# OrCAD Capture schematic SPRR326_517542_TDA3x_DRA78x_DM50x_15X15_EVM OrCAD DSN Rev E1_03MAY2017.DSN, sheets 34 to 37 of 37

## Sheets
34 SH12 - MUX D/E/F/G/H: size C; rev: A
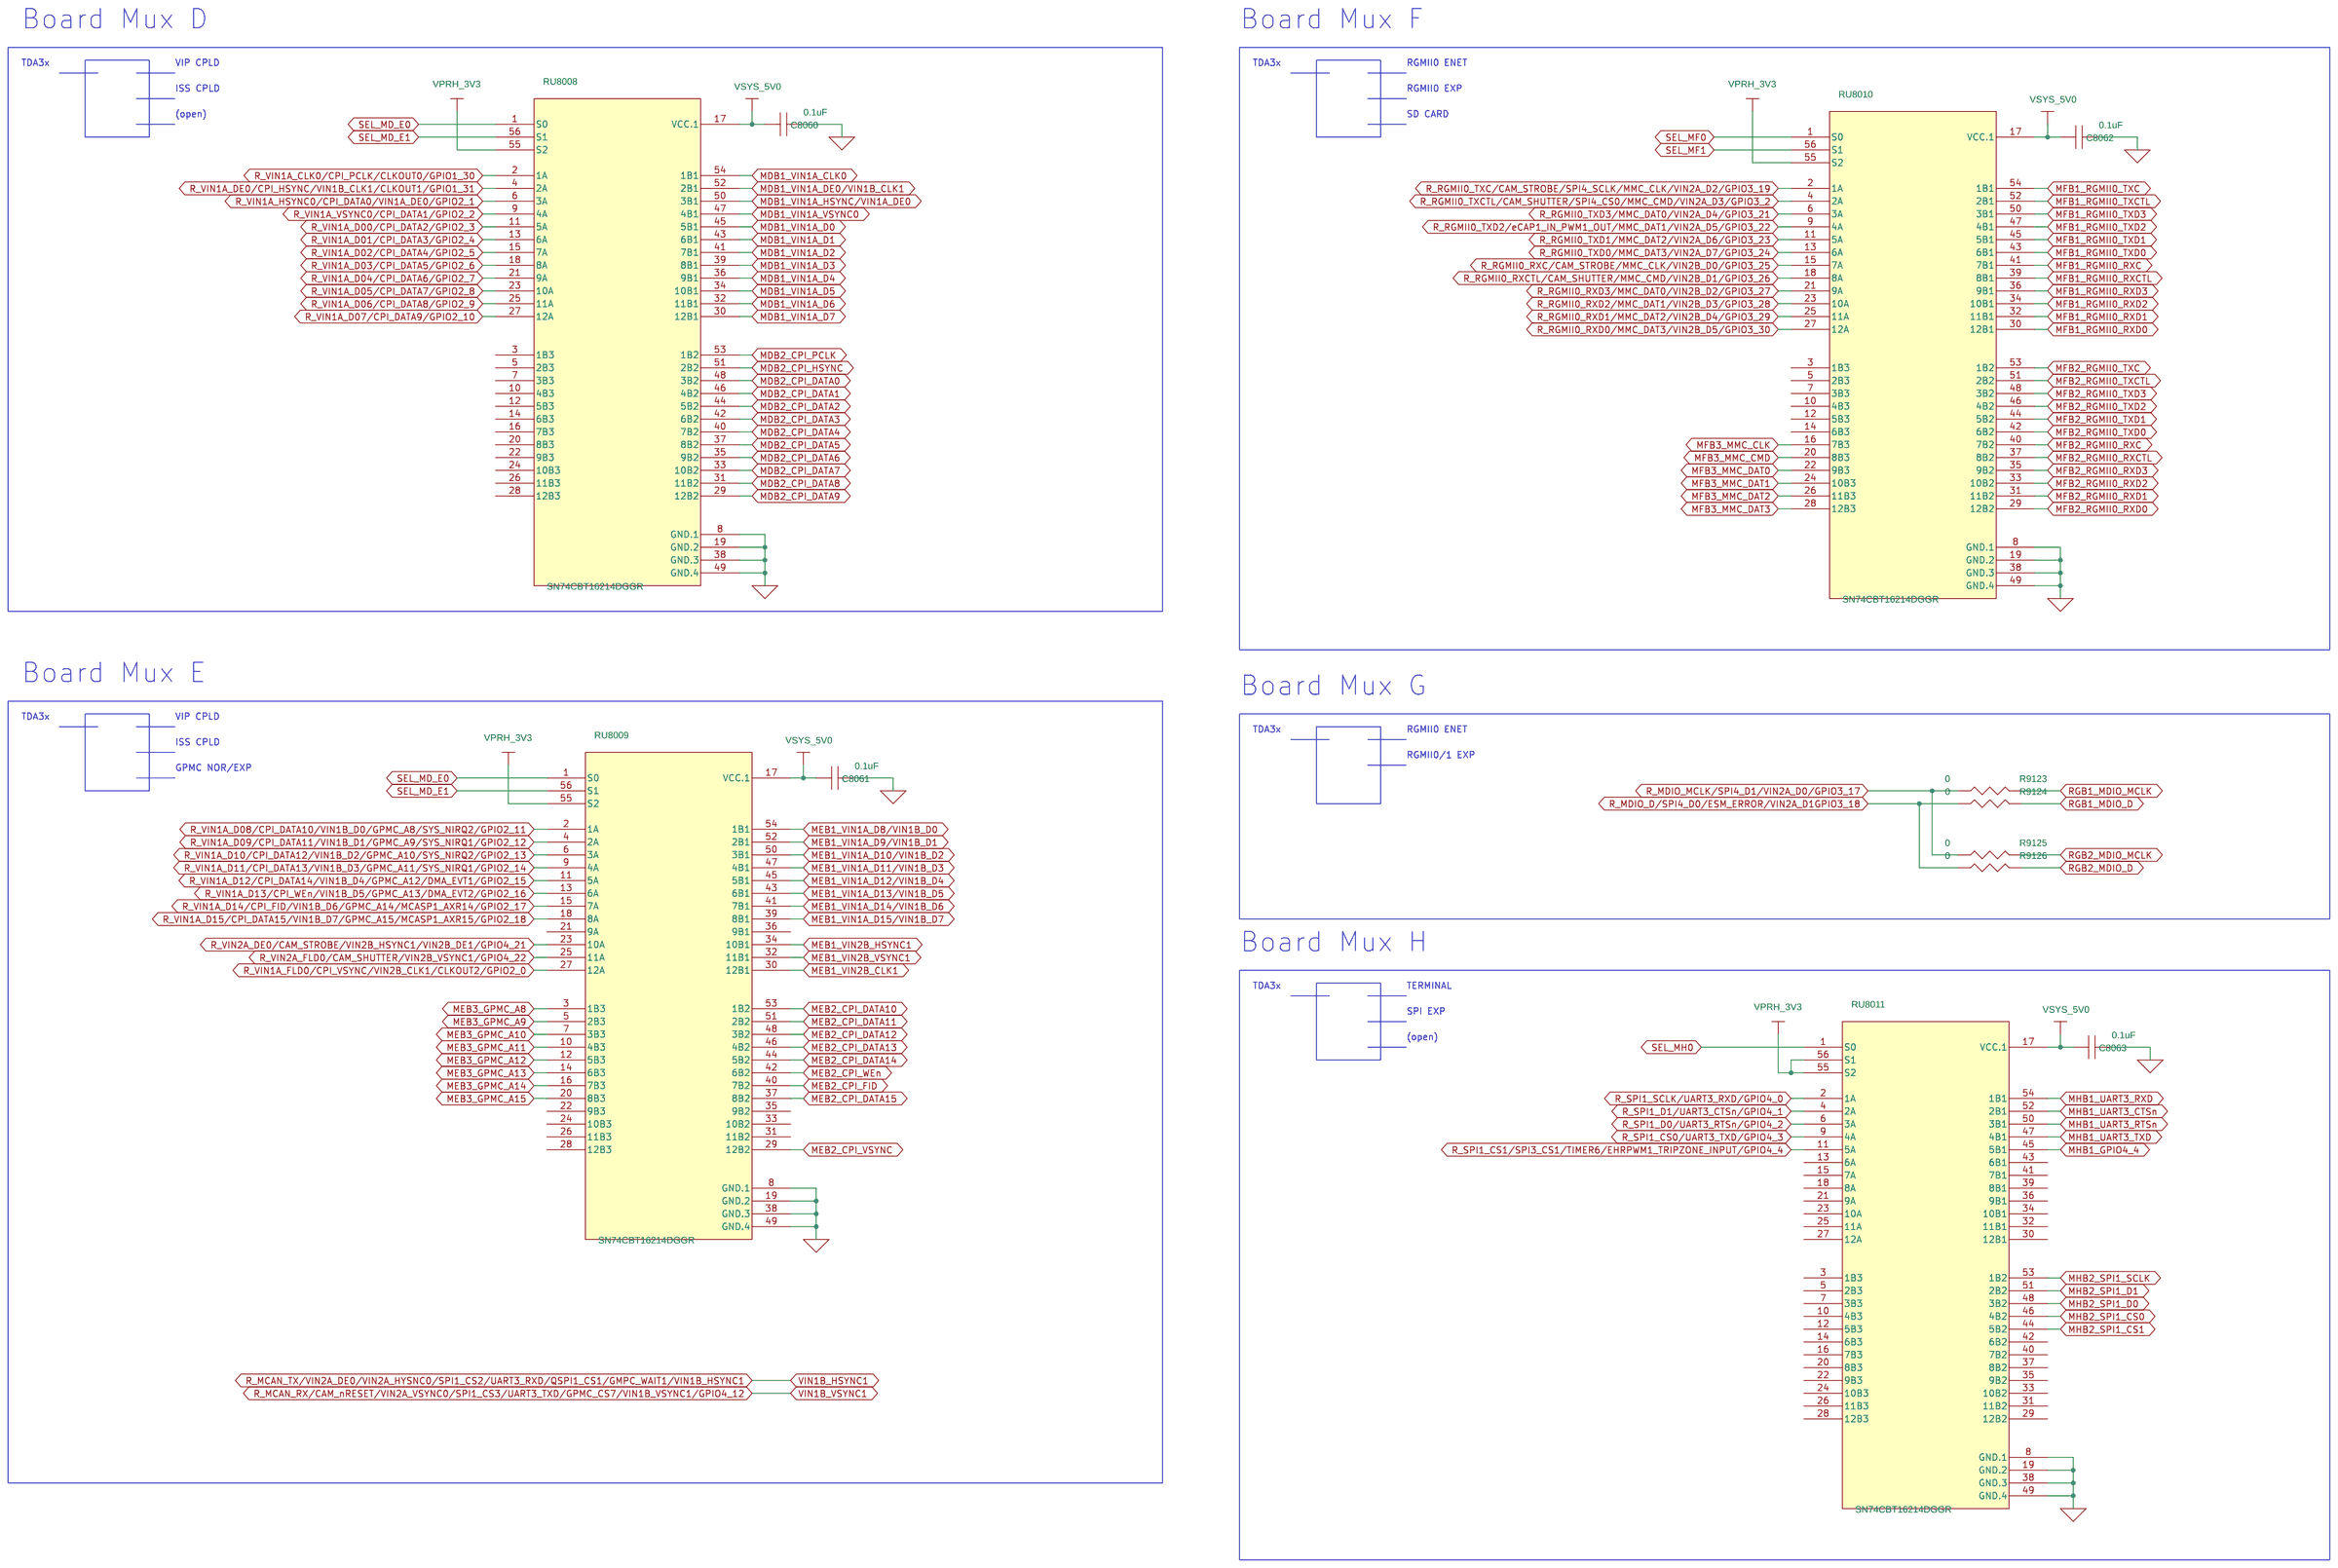
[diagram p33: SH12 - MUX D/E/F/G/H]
35 SH17 - CAN/SAFETY MCU: size C; rev: D
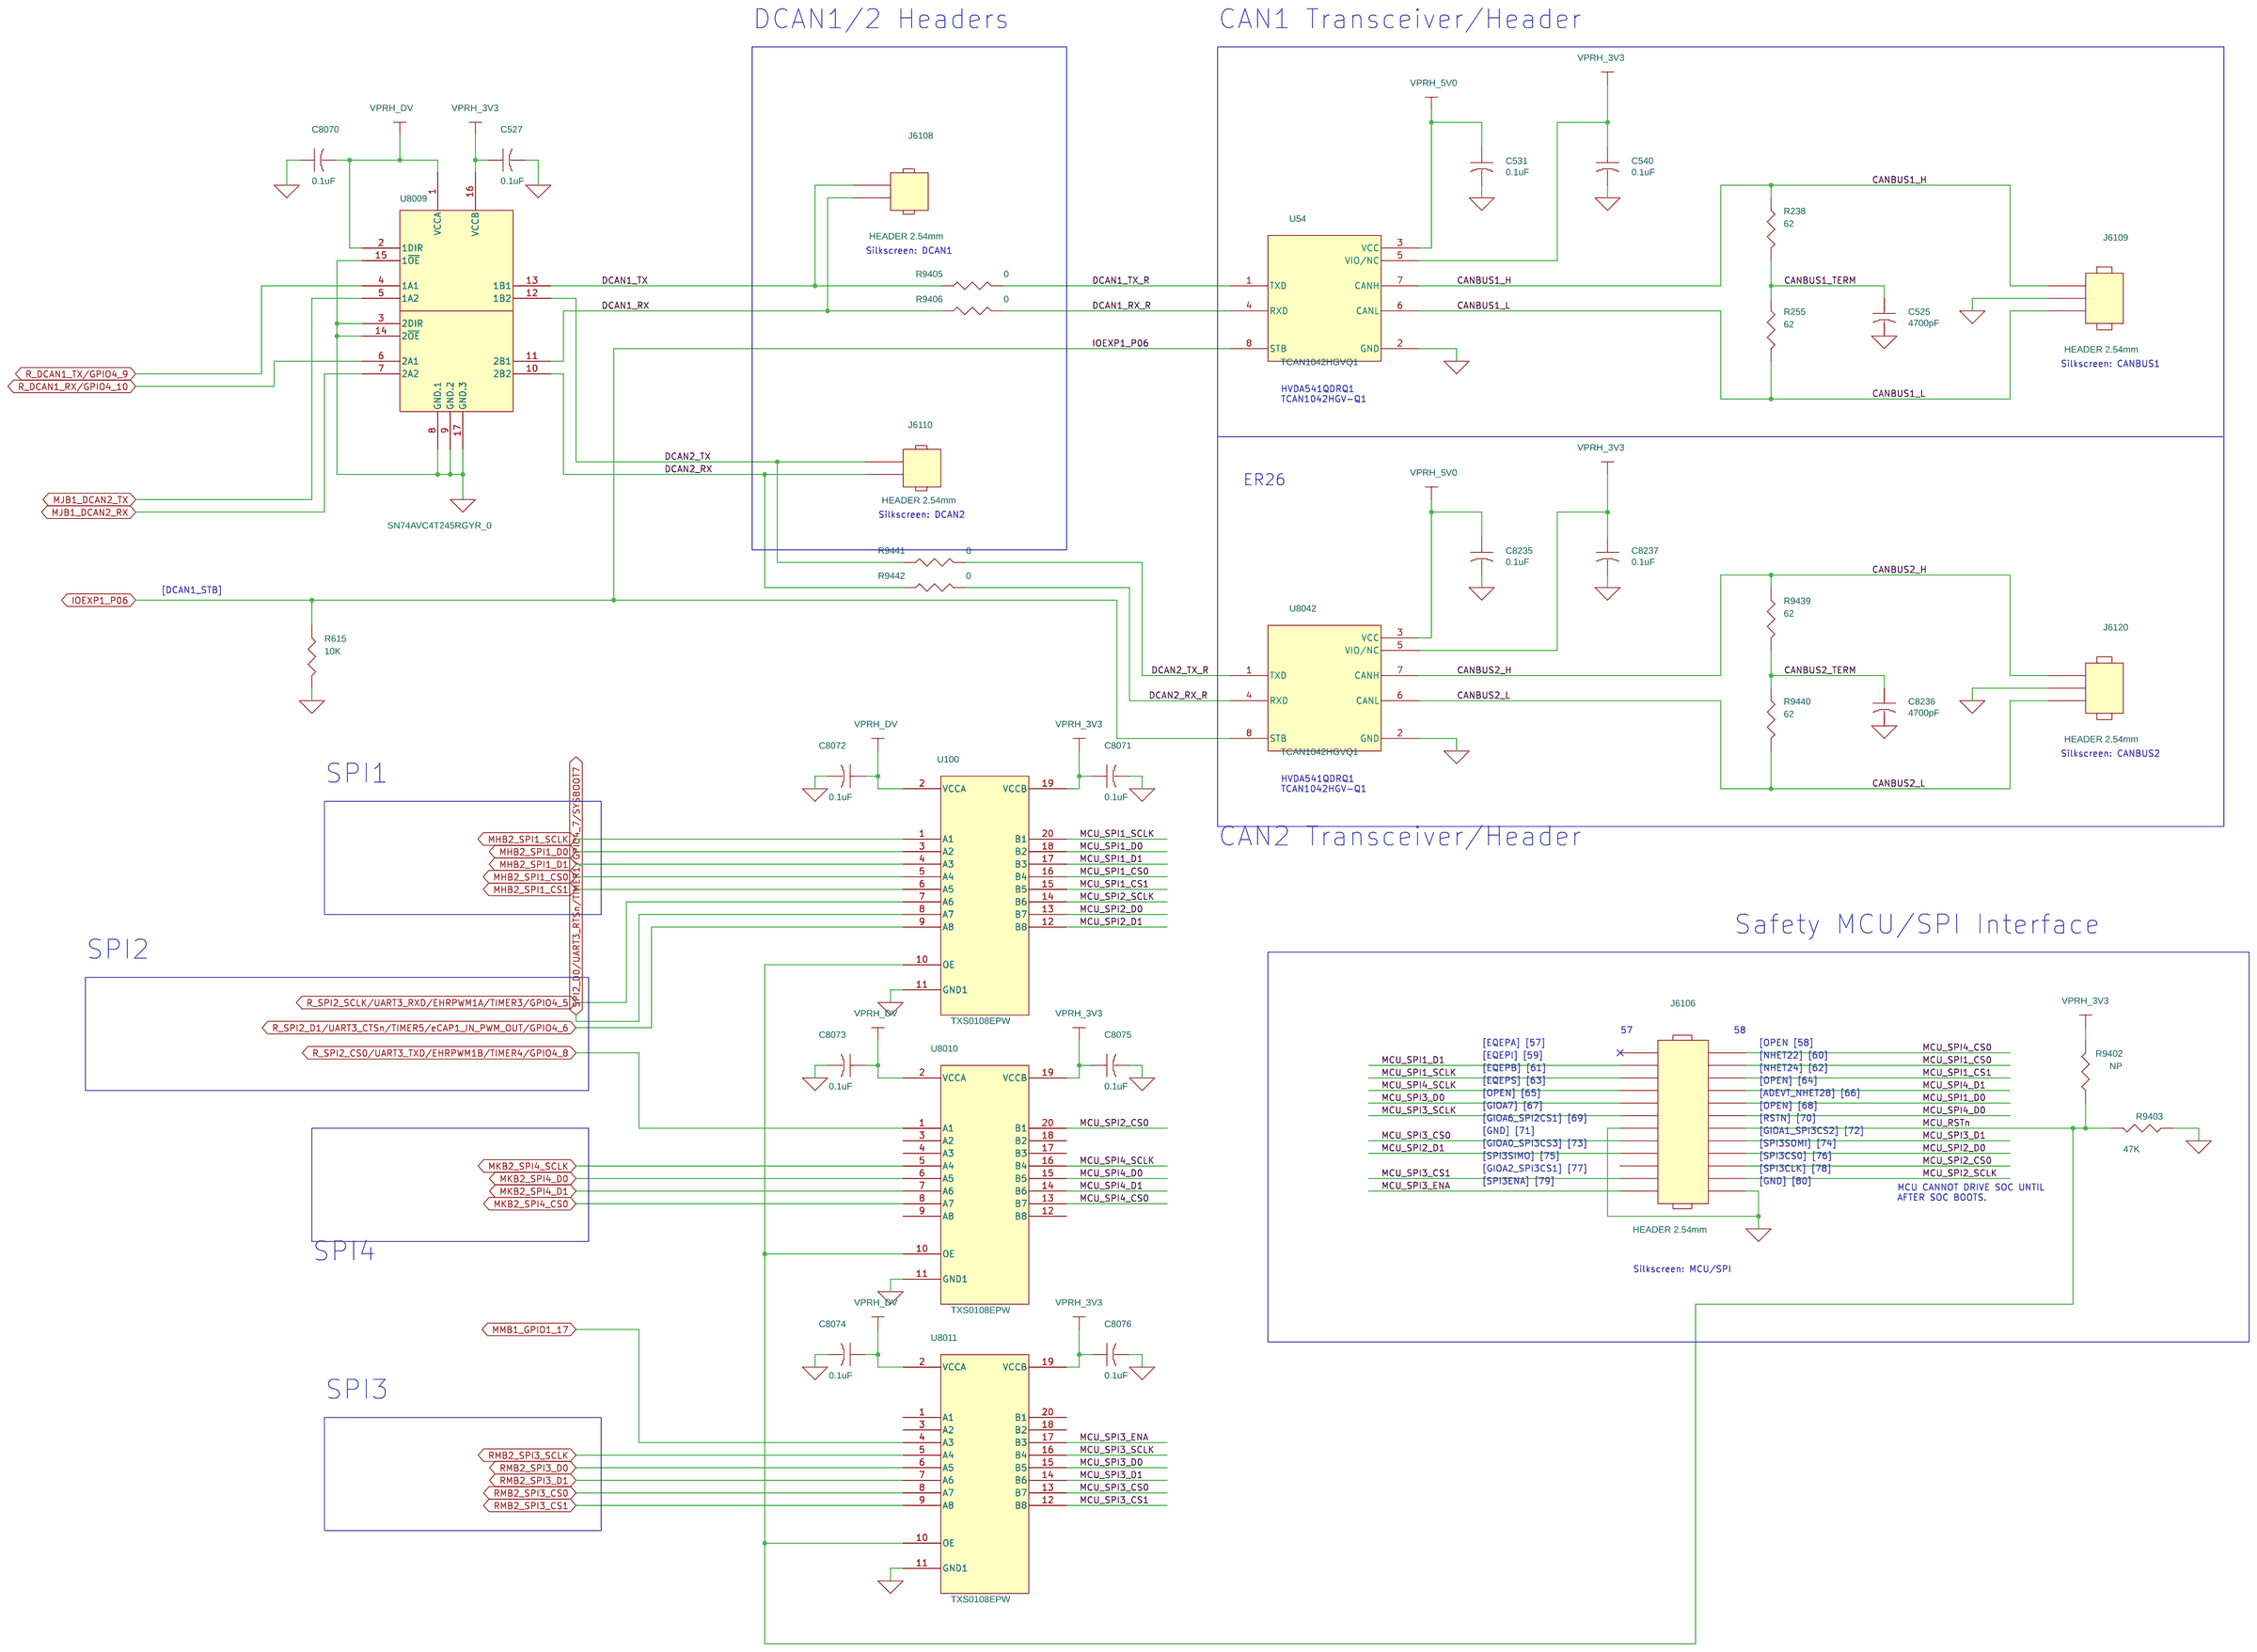
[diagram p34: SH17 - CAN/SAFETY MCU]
36 SH14 - SD CARD/EEPROM/TMP: size C; rev: D
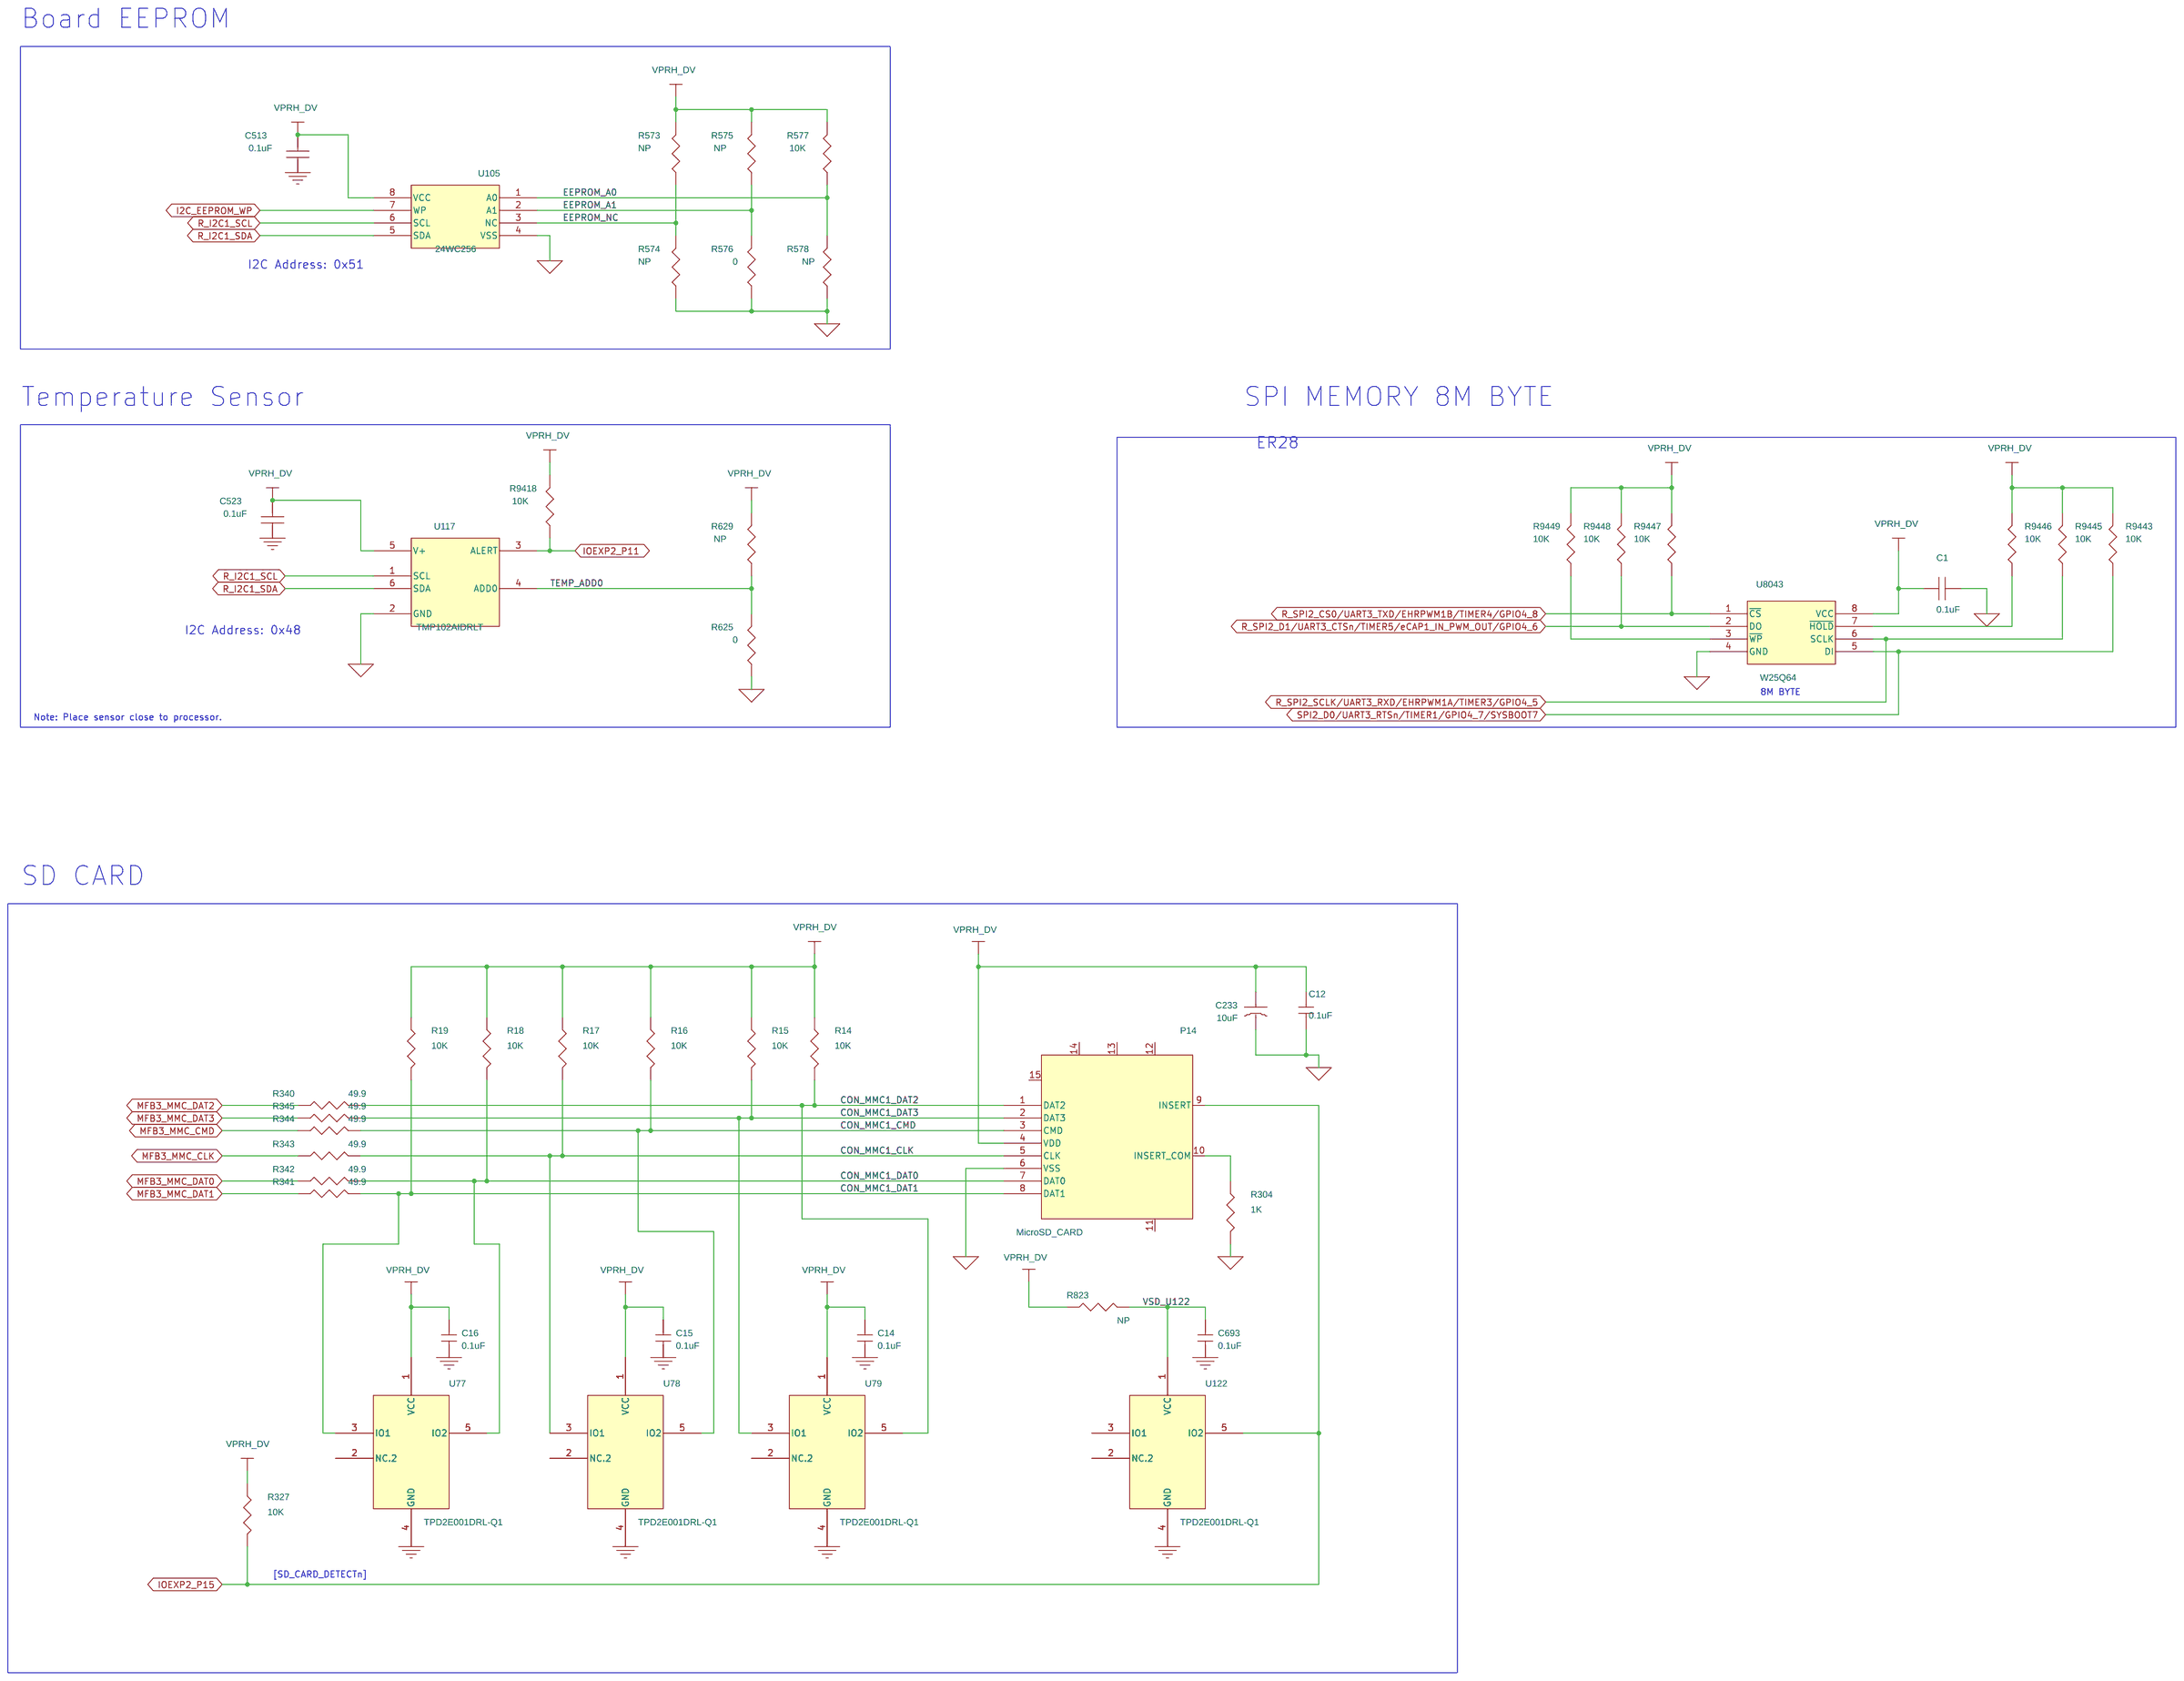
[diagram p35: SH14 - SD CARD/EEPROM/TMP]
37 SH23 - POWER BENCH/MONITORS: size C; rev: A
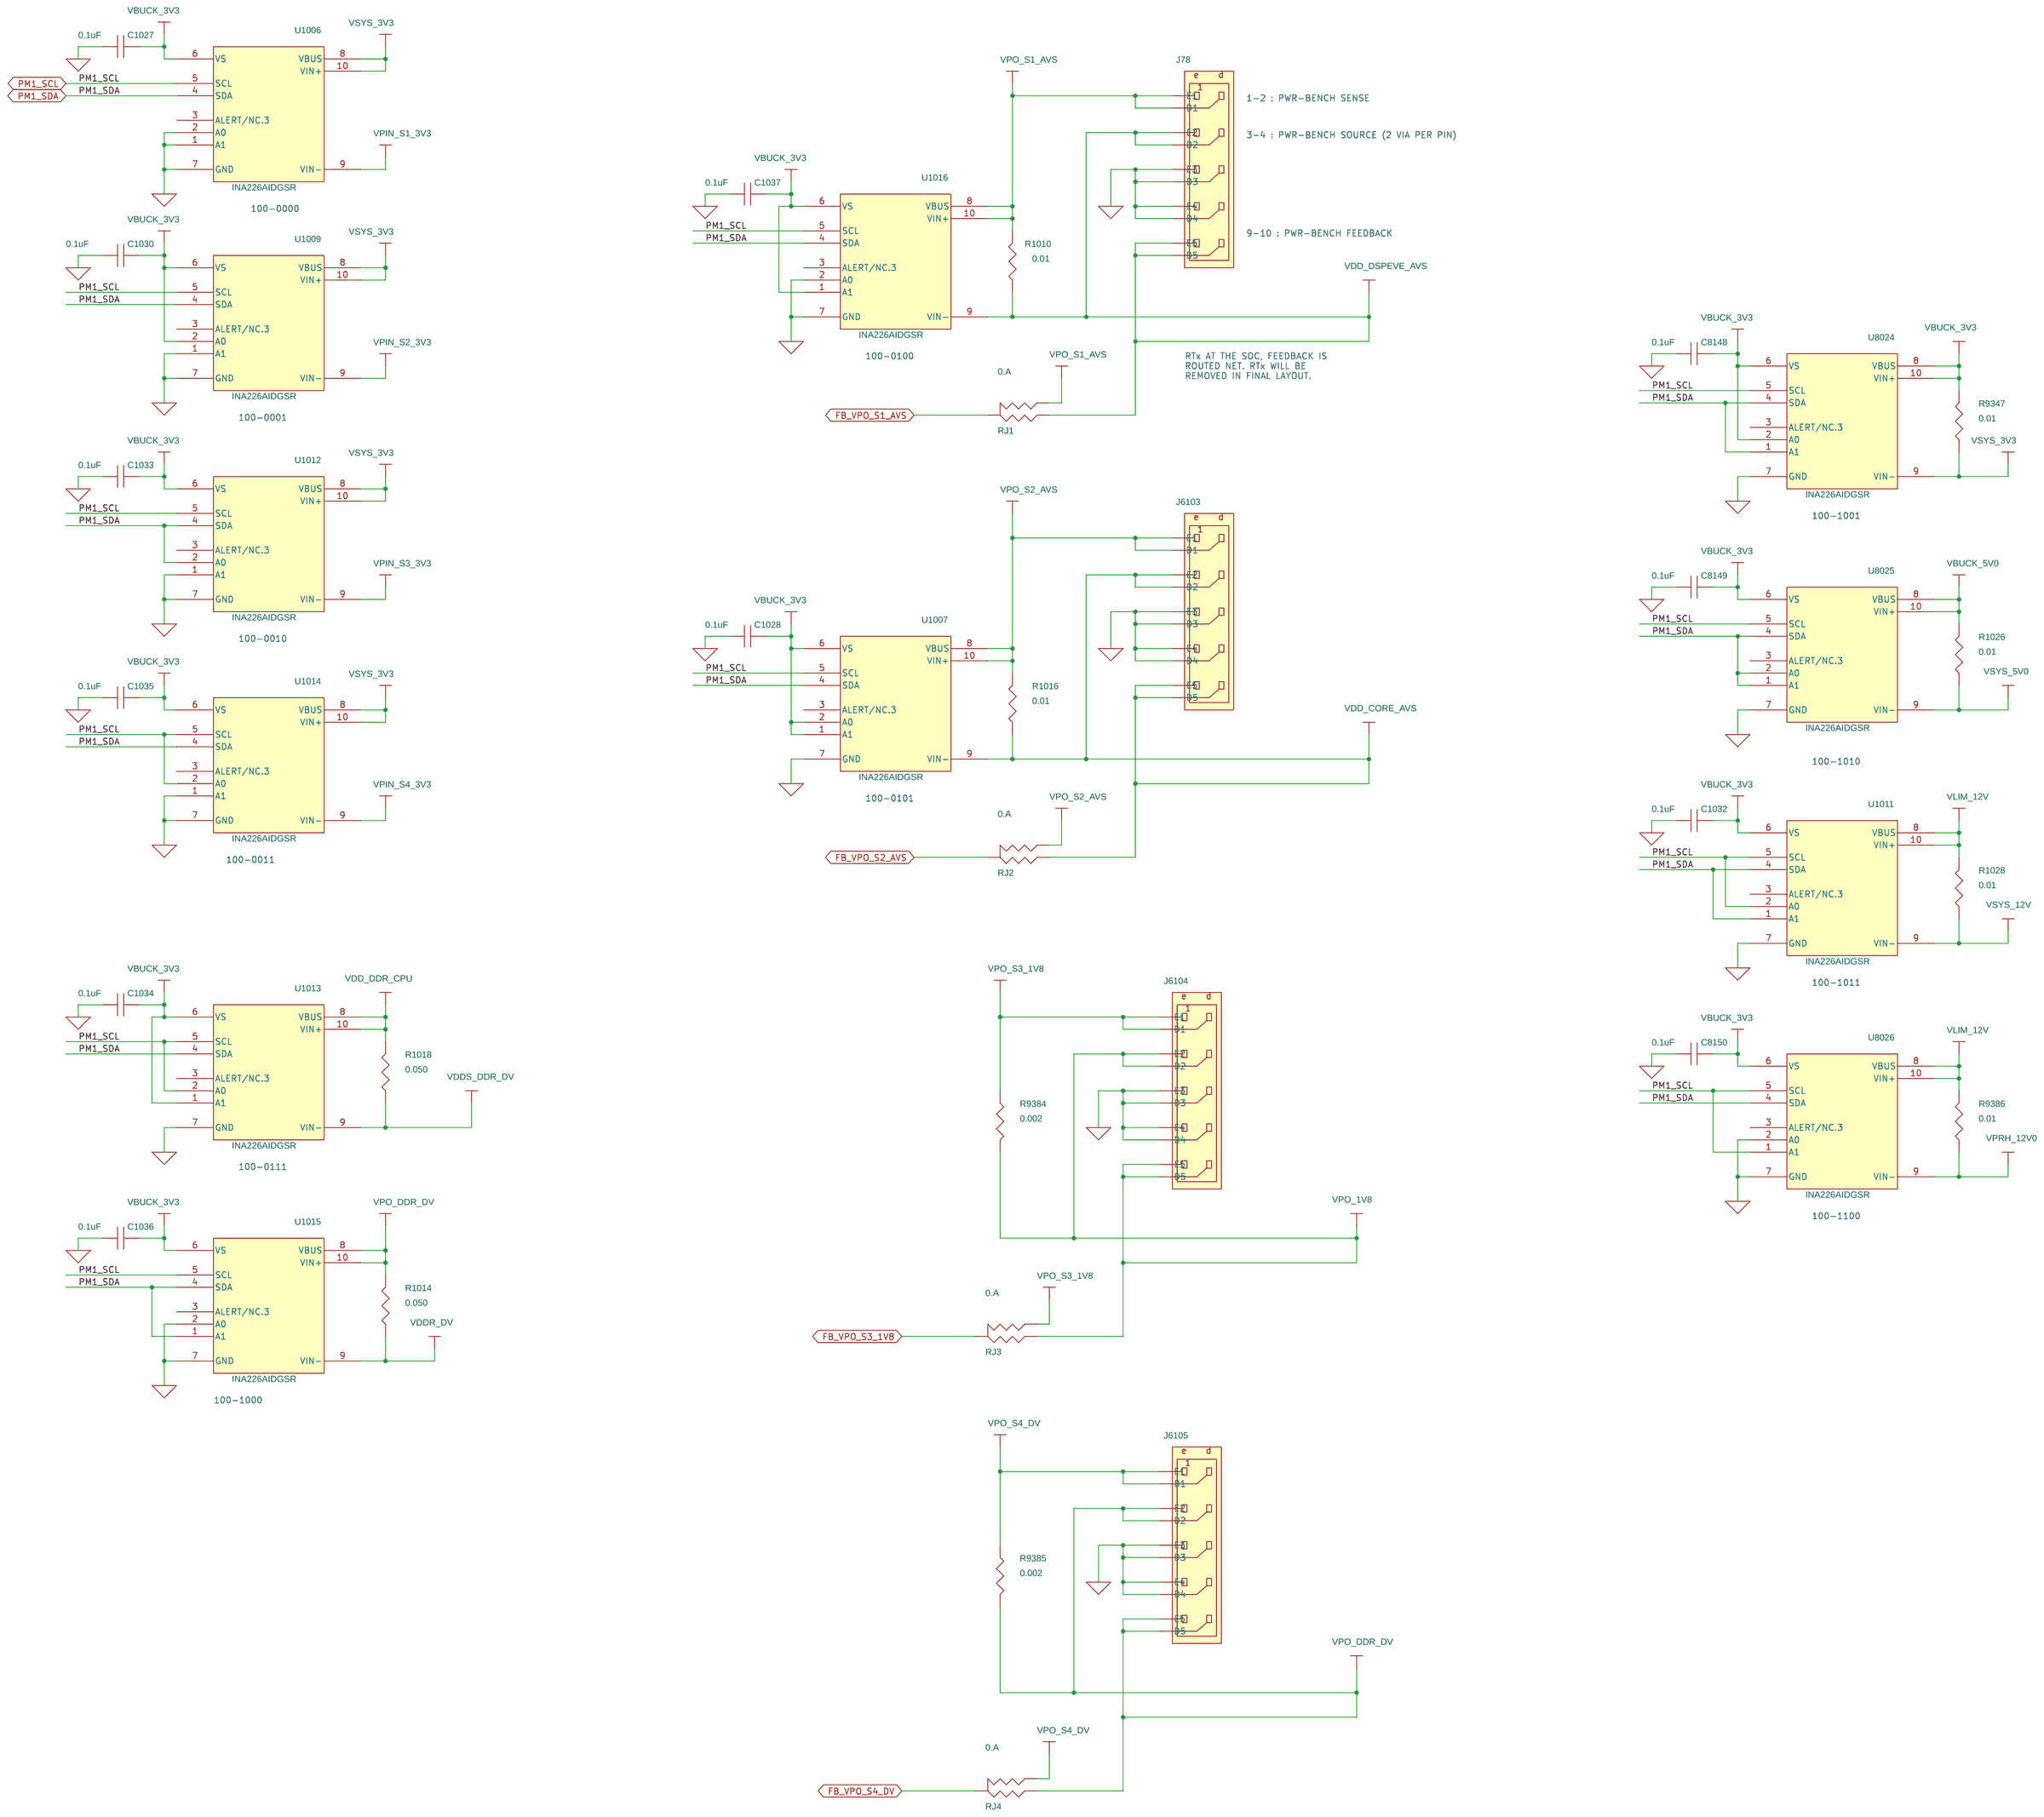
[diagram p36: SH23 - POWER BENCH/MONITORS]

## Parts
sheet SH12 - MUX D/E/F/G/H
C8060  0.1uF  [c402-25]
C8061  0.1uF  [c402-25]
C8062  0.1uF  [c402-25]
C8063  0.1uF  [c402-25]
R9123  0  [r201-6p6spc]
R9124  0  [r201-6p6spc]
R9125  0  [r201-6p6spc]
R9126  0  [r201-6p6spc]
RU8008  SN74CBT16214DGGR  [dgg56-12x80]
RU8009  SN74CBT16214DGGR  [dgg56-12x80]
RU8010  SN74CBT16214DGGR  [dgg56-12x80]
RU8011  SN74CBT16214DGGR  [dgg56-12x80]
sheet SH14 - SD CARD/EEPROM/TMP
C1  0.1uF  [c402-25]
C12  0.1uF  [c402-25]
C14  0.1uF  [c402-25]
C15  0.1uF  [c402-25]
C16  0.1uF  [c402-25]
C233  10uF  [c603-35x45]
C513  0.1uF  [c402-25]
C523  0.1uF  [c402-25]
C693  0.1uF  [c402-25]
P14  MicroSD_CARD  [molex-49225-201]
R14  10K  [r402-25]
R15  10K  [r402-25]
R16  10K  [r402-25]
R17  10K  [r402-25]
R18  10K  [r402-25]
R19  10K  [r402-25]
R304  1K  [r402-25]
R327  10K  [r402-25]
R340  49.9  [r402-25]
R341  49.9  [r402-25]
R342  49.9  [r402-25]
R343  49.9  [r402-25]
R344  49.9  [r402-25]
R345  49.9  [r402-25]
R573  NP  [r402-25]
R574  NP  [r402-25]
R575  NP  [r402-25]
R576  0  [r402-25]
R577  10K  [r402-25]
R578  NP  [r402-25]
R625  0  [r402-25]
R629  NP  [r402-25]
R823  NP  [r402-25]
R9418  10K  [r402-25]
R9443  10K  [r201-18p5x15]
R9445  10K  [r201-18p5x15]
R9446  10K  [r201-18p5x15]
R9447  10K  [r201-18p5x15]
R9448  10K  [r201-18p5x15]
R9449  10K  [r201-18p5x15]
U77  TPD2E001DRL-Q1  [drl5-12x40]
U78  TPD2E001DRL-Q1  [drl5-12x40]
U79  TPD2E001DRL-Q1  [drl5-12x40]
U105  24WC256  [so8-25x75-295]
U117  TMP102AIDRLT  [drl6-12x30]
U122  TPD2E001DRL-Q1  [drl5-12x40]
U8043  W25Q64  [so8-25x75-295]
sheet SH17 - CAN/SAFETY MCU
C525  4700pF  [c402-25]
C527  0.1uF  [c402-25]
C531  0.1uF  [c402-25]
C540  0.1uF  [c402-25]
C8070  0.1uF  [c402-25]
C8071  0.1uF  [c402-25]
C8072  0.1uF  [c402-25]
C8073  0.1uF  [c402-25]
C8074  0.1uF  [c402-25]
C8075  0.1uF  [c402-25]
C8076  0.1uF  [c402-25]
C8235  0.1uF  [c402-25]
C8236  4700pF  [c402-25]
C8237  0.1uF  [c402-25]
J6106  HEADER 2.54mm  [jump2x12-6040]
J6108  HEADER 2.54mm  [JUMP1X2-6040]
J6109  HEADER 2.54mm  [JUMP1X3-6040]
J6110  HEADER 2.54mm  [JUMP1X2-6040]
J6120  HEADER 2.54mm  [JUMP1X3-6040]
R238  62  [r1206-40x70]
R255  62  [r1206-40x70]
R615  10K  [r402-25]
R9402  NP  [r402-25]
R9403  47K  [r402-25]
R9405  0  [r402-25]
R9406  0  [r402-25]
R9439  62  [r1206-40x70]
R9440  62  [r1206-40x70]
R9441  0  [r402-25]
R9442  0  [r402-25]
U54  TCAN1042HGVQ1  [so8-25x75]
U100  TXS0108EPW  [pw20-14x70]
U8009  SN74AVC4T245RGYR_0  [rgy16-12x34]
U8010  TXS0108EPW  [pw20-14x70]
U8011  TXS0108EPW  [pw20-14x70]
U8042  TCAN1042HGVQ1  [so8-25x75]
sheet SH23 - POWER BENCH/MONITORS
C1027  0.1uF  [c402-25]
C1028  0.1uF  [c402-25]
C1030  0.1uF  [c402-25]
C1032  0.1uF  [c402-25]
C1033  0.1uF  [c402-25]
C1034  0.1uF  [c402-25]
C1035  0.1uF  [c402-25]
C1036  0.1uF  [c402-25]
C1037  0.1uF  [c402-25]
C8148  0.1uF  [c402-25]
C8149  0.1uF  [c402-25]
C8150  0.1uF  [c402-25]
J78  Qte=0.5  [conn2x5-40x100-tsm]
J6103  Qte=0.5  [conn2x5-40x100-tsm]
J6104  Qte=0.5  [conn2x5-40x100-tsm]
J6105  Qte=0.5  [conn2x5-40x100-tsm]
R1010  0.01  [r1206-40X70]
R1014  0.050  [r603-35x45]
R1016  0.01  [r1206-40X70]
R1018  0.050  [r603-35x45]
R1026  0.01  [r1206-40X70]
R1028  0.01  [r1206-40X70]
R9347  0.01  [r1206-40X70]
R9384  0.002  [r1206-40x70]
R9385  0.002  [r1206-40x70]
R9386  0.01  [r1206-40X70]
RJ1  0.A  [JMP402-25]
RJ2  0.A  [JMP402-25]
RJ3  0.A  [JMP402-25]
RJ4  0.A  [JMP402-25]
U1006  INA226AIDGSR  [dgs10-11x60]
U1007  INA226AIDGSR  [dgs10-11x60]
U1009  INA226AIDGSR  [dgs10-11x60]
U1011  INA226AIDGSR  [dgs10-11x60]
U1012  INA226AIDGSR  [dgs10-11x60]
U1013  INA226AIDGSR  [dgs10-11x60]
U1014  INA226AIDGSR  [dgs10-11x60]
U1015  INA226AIDGSR  [dgs10-11x60]
U1016  INA226AIDGSR  [dgs10-11x60]
U8024  INA226AIDGSR  [dgs10-11x60]
U8025  INA226AIDGSR  [dgs10-11x60]
U8026  INA226AIDGSR  [dgs10-11x60]

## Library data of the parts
C1027 C1028 C1030 C1032-C1037 C8060-C8063 C8148-C8150 = CAP_NP: Part #: 104446-1100R
R9123-R9126 = R_1: Part #: 103158-0001R
RU8008-RU8011 = SN74CBT16214DGGR_0: Part #: 102513-0001R
C1 = CAP_NP: Part #: 101587-1100R
C12 C14-C16 C693 = Cap_100nF_Cermc_16V_10%_603_4: Part #: 104446-1100R
C233 = CAP: Part #: 102963-0101R
C513 C523 = CAP_.1_uF_10%_0603: Part #: 104446-1100R
P14 = MM_CARD_0: Part #: 103053-0001R
R14-R19 R327 = RESISTOR: Part #: 101370-1003R
R304 = RESISTOR: Part #: 101370-1002R
R340-R345 = RESISTOR: Part #: 102145-4990R
R573-R575 R629 R9402 = R: Part #: R0402-NOPOP
R576 R625 = R_1: Part #: 101370-0001R
R577 R615 R9418 = R: Part #: 101370-1003R
R578 = R_1: Part #: R0402-NOPOP
R823 = RESISTOR: Part #: R0402-NOPOP
R9443 R9447-R9449 = R: Part #: 103158-1003R
R9445 R9446 = RESISTOR_1: Part #: 103158-1003R
U77-U79 U122 = TPDE0001RSE_0: Part #: 102728-0001R
U105 = 24WC256: Part #: 102235-0001R
U117 = TMP102AIDRLT: Part #: 104192-0001R
U8043 = SPI_EEPROM_2: Part #: 104052-0001R
C525 C8236 = CAP: Part #: 103217-1472R
C527 C531 C540 C8070-C8076 C8235 C8237 = CAP: Part #: 104446-1100R
J6106 = HEADER_12X2: Part #: 100116-0012R
J6108 J6110 = HEADER_2: Part #: 100115-0002R
J6109 J6120 = HEADER_3: Part #: NO-POP
R238 R255 R9439 R9440 = R: Part #: 100155-6200R
R9403 = R: Part #: 101370-4703R
R9405 R9406 R9441 R9442 = R: Part #: 101370-0001R
U54 U8042 = SN65HVDA541: Part #: 104828-0001R
U100 U8010 U8011 = TXB0108PWR_0: Part #: 103666-0001R
U8009 = SN74AVC4T245RGYR_0: Part #: 102649-0245R
J78 J6103-J6105 = HE10_10MD_ASP-128562-04_0: GPAO_ART: 05600038255AA; Part #: 100932-0005R
R1010 R1016 R1026 R1028 R9347 R9386 = R: Part #: 102598-0001R
R1014 R1018 = R: Part #: 104469-0005R
R9384 R9385 = R: Part #: 104297-0002R
RJ1-RJ4 = RJUMP3: Part #: 101370-0001R
U1006 U1007 U1009 U1011-U1016 U8024-U8026 = INA220IDCN_2: Part #: 103928-0001R

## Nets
GND: C1.2 C12.2 C14.2 C15.2 C16.2 C233.2 C513.1 C523.1 C525.2 C527.2 C531.2 C540.2 C693.2 C1027.1 C1028.1 C1030.1 C1032.1 C1033.1 C1034.1 C1035.1 C1036.1 C1037.1 C8060.2 C8061.2 C8062.2 C8063.2 C8070.1 C8071.2 C8072.2 C8073.2 C8074.2 C8075.2 C8076.2 C8148.1 C8149.1 C8150.1 C8235.2 C8236.2 C8237.2 J78.5(E3) J78.6(D3) J78.7(E4) J78.8(D4) J6103.5(E3) J6103.6(D3) J6103.7(E4) J6103.8(D4) J6104.5(E3) J6104.6(D3) J6104.7(E4) J6104.8(D4) J6105.5(E3) J6105.6(D3) J6105.7(E4) J6105.8(D4) J6106.13 J6106.24 J6109.2 J6120.2 P14.6(VSS) R304.2 R574.2 R576.2 R578.2 R615.2 R625.2 R9403.2 RU8008.8(GND.1) RU8008.19(GND.2) RU8008.38(GND.3) RU8008.49(GND.4) RU8009.8(GND.1) RU8009.19(GND.2) RU8009.38(GND.3) RU8009.49(GND.4) RU8010.8(GND.1) RU8010.19(GND.2) RU8010.38(GND.3) RU8010.49(GND.4) RU8011.8(GND.1) RU8011.19(GND.2) RU8011.38(GND.3) RU8011.49(GND.4) U54.2(GND) U77.4(GND) U78.4(GND) U79.4(GND) U100.11(GND1) U105.4(VSS) U117.2(GND) U122.4(GND) U1006.1(A1) U1006.2(A0) U1006.7(GND) U1007.7(GND) U1009.1(A1) U1009.7(GND) U1011.7(GND) U1012.1(A1) U1012.7(GND) U1013.7(GND) U1014.1(A1) U1014.7(GND) U1015.2(A0) U1015.7(GND) U1016.2(A0) U1016.7(GND) U8009.3(2DIR) U8009.8(GND.1) U8009.9(GND.2) U8009.14(2~{OE}) U8009.15(1~{OE}) U8009.17(GND.3) U8010.11(GND1) U8011.11(GND1) U8024.7(GND) U8025.7(GND) U8026.2(A0) U8026.7(GND) U8042.2(GND) U8043.4(GND) ; also on sheet 4 5 6 7 8 9 10 11 12 13 14 15 16 17 18 19 20 21 22 23 25 26 27 28 29 30 31 32
MDB1_VIN1A_DE0/VIN1B_CLK1: RU8008.52(2B1) ; also on sheet 27
MDB1_VIN1A_HSYNC/VIN1A_DE0: RU8008.50(3B1) ; also on sheet 27
MEB1_VIN1A_D8/VIN1B_D0: RU8009.54(1B1) ; also on sheet 27
MEB1_VIN1A_D9/VIN1B_D1: RU8009.52(2B1) ; also on sheet 27
MEB1_VIN1A_D10/VIN1B_D2: RU8009.50(3B1) ; also on sheet 27
MEB1_VIN1A_D11/VIN1B_D3: RU8009.47(4B1) ; also on sheet 27
MEB1_VIN1A_D12/VIN1B_D4: RU8009.45(5B1) ; also on sheet 27
MEB1_VIN1A_D13/VIN1B_D5: RU8009.43(6B1) ; also on sheet 27
MEB1_VIN1A_D14/VIN1B_D6: RU8009.41(7B1) ; also on sheet 27
MEB1_VIN1A_D15/VIN1B_D7: RU8009.39(8B1) ; also on sheet 27
R_MDIO_D/SPI4_D0/ESM_ERROR/VIN2A_D1GPIO3_18: R9124.2 R9126.2 ; also on sheet 7
VDD_CORE_AVS: J6103.3(E2) J6103.4(D2) J6103.9(E5) J6103.10(D5) R1016.2 RJ2.1 U1007.9(VIN-) ; also on sheet 4 5
VDD_DDR_CPU: R1018.1 U1013.8(VBUS) U1013.10(VIN+) ; also on sheet 14
VDD_DSPEVE_AVS: J78.3(E2) J78.4(D2) J78.9(E5) J78.10(D5) R1010.2 RJ1.1 U1016.9(VIN-) ; also on sheet 4 5
VDDR_DV: R1014.2 U1015.9(VIN-) ; also on sheet 6
VDDS_DDR_DV: R1018.2 U1013.9(VIN-) ; also on sheet 5
CANBUS1_H: J6109.1 R238.1 U54.7(CANH)
CANBUS1_L: J6109.3 R255.2 U54.6(CANL)
CANBUS1_TERM: C525.1 R238.2 R255.1
CANBUS2_H: J6120.1 R9439.1 U8042.7(CANH)
CANBUS2_L: J6120.3 R9440.2 U8042.6(CANL)
CANBUS2_TERM: C8236.1 R9439.2 R9440.1
CON_MMC1_CLK: P14.5(CLK) R17.2 R343.2 U78.3(IO1)
CON_MMC1_CMD: P14.3(CMD) R16.2 R344.2 U78.5(IO2)
CON_MMC1_DAT0: P14.7(DAT0) R18.2 R342.2 U77.5(IO2)
CON_MMC1_DAT1: P14.8(DAT1) R19.2 R341.2 U77.3(IO1)
CON_MMC1_DAT2: P14.1(DAT2) R14.2 R340.2 U79.5(IO2)
CON_MMC1_DAT3: P14.2(DAT3) R15.2 R345.2 U79.3(IO1)
DCAN1_RX: J6108.2 R9406.1 U8009.11(2B1)
DCAN1_RX_R: R9406.2 U54.4(RXD)
DCAN1_TX: J6108.1 R9405.1 U8009.13(1B1)
DCAN1_TX_R: R9405.2 U54.1(TXD)
DCAN2_RX: J6110.2 R9442.1 U8009.10(2B2)
DCAN2_RX_R: R9442.2 U8042.4(RXD)
DCAN2_TX: J6110.1 R9441.1 U8009.12(1B2)
DCAN2_TX_R: R9441.2 U8042.1(TXD)
EEPROM_A0: R577.2 R578.1 U105.1(A0)
EEPROM_A1: R575.2 R576.1 U105.2(A1)
EEPROM_NC: R573.2 R574.1 U105.3(NC)
ENET_INTSn: RU8011.45(5B1) ; also on sheet 7 11
FB_VPO_S1_AVS: RJ1.2 ; also on sheet 13
FB_VPO_S2_AVS: RJ2.2 ; also on sheet 13
FB_VPO_S3_1V8: RJ3.2 ; also on sheet 13
FB_VPO_S4_DV: RJ4.2 ; also on sheet 13
I2C_EEPROM_WP: U105.7(WP) ; also on sheet 31
IOEXP1_P06: R615.1 U54.8(STB) U8042.8(STB) ; also on sheet 8
IOEXP2_P11: R9418.2 U117.3(ALERT) ; also on sheet 8
IOEXP2_P15: P14.9(INSERT) R327.2 U122.5(IO2) ; also on sheet 8
MCU_RSTn: J6106.14 R9402.2 R9403.1 U100.10(OE) U8010.10(OE) U8011.10(OE)
MCU_SPI1_CS0: J6106.4 U100.16(B4)
MCU_SPI1_CS1: J6106.6 U100.15(B5)
MCU_SPI1_D0: J6106.10 U100.18(B2)
MCU_SPI1_D1: J6106.3 U100.17(B3)
MCU_SPI1_SCLK: J6106.5 U100.20(B1)
MCU_SPI2_CS0: J6106.20 U8010.20(B1)
MCU_SPI2_D0: J6106.18 U100.13(B7)
MCU_SPI2_D1: J6106.17 U100.12(B8)
MCU_SPI2_SCLK: J6106.22 U100.14(B6)
MCU_SPI3_CS0: J6106.15 U8011.13(B7)
MCU_SPI3_CS1: J6106.21 U8011.12(B8)
MCU_SPI3_D0: J6106.9 U8011.15(B5)
MCU_SPI3_D1: J6106.16 U8011.14(B6)
MCU_SPI3_ENA: J6106.23 U8011.17(B3)
MCU_SPI3_SCLK: J6106.11 U8011.16(B4)
MCU_SPI4_CS0: J6106.2 U8010.13(B7)
MCU_SPI4_D0: J6106.12 U8010.15(B5)
MCU_SPI4_D1: J6106.8 U8010.14(B6)
MCU_SPI4_SCLK: J6106.7 U8010.16(B4)
MDB1_VIN1A_CLK0: RU8008.54(1B1) ; also on sheet 27
MDB1_VIN1A_D0: RU8008.45(5B1) ; also on sheet 27
MDB1_VIN1A_D1: RU8008.43(6B1) ; also on sheet 27
MDB1_VIN1A_D2: RU8008.41(7B1) ; also on sheet 27
MDB1_VIN1A_D3: RU8008.39(8B1) ; also on sheet 27
MDB1_VIN1A_D4: RU8008.36(9B1) ; also on sheet 27
MDB1_VIN1A_D5: RU8008.34(10B1) ; also on sheet 27
MDB1_VIN1A_D6: RU8008.32(11B1) ; also on sheet 27
MDB1_VIN1A_D7: RU8008.30(12B1) ; also on sheet 27
MDB1_VIN1A_VSYNC0: RU8008.47(4B1) ; also on sheet 27
MDB2_CPI_DATA0: RU8008.48(3B2) ; also on sheet 27
MDB2_CPI_DATA1: RU8008.46(4B2) ; also on sheet 27
MDB2_CPI_DATA2: RU8008.44(5B2) ; also on sheet 27
MDB2_CPI_DATA3: RU8008.42(6B2) ; also on sheet 27
MDB2_CPI_DATA4: RU8008.40(7B2) ; also on sheet 27
MDB2_CPI_DATA5: RU8008.37(8B2) ; also on sheet 27
MDB2_CPI_DATA6: RU8008.35(9B2) ; also on sheet 27
MDB2_CPI_DATA7: RU8008.33(10B2) ; also on sheet 27
MDB2_CPI_DATA8: RU8008.31(11B2) ; also on sheet 27
MDB2_CPI_DATA9: RU8008.29(12B2) ; also on sheet 27
MDB2_CPI_HSYNC: RU8008.51(2B2) ; also on sheet 27
MDB2_CPI_PCLK: RU8008.53(1B2) ; also on sheet 27
MEB1_VIN2B_CLK1: RU8009.30(12B1) ; also on sheet 27
MEB1_VIN2B_HSYNC1: RU8009.34(10B1) ; also on sheet 27
MEB1_VIN2B_VSYNC1: RU8009.32(11B1) ; also on sheet 27
MEB2_CPI_DATA10: RU8009.53(1B2) ; also on sheet 27
MEB2_CPI_DATA11: RU8009.51(2B2) ; also on sheet 27
MEB2_CPI_DATA12: RU8009.48(3B2) ; also on sheet 27
MEB2_CPI_DATA13: RU8009.46(4B2) ; also on sheet 27
MEB2_CPI_DATA14: RU8009.44(5B2) ; also on sheet 27
MEB2_CPI_DATA15: RU8009.37(8B2) ; also on sheet 27
MEB2_CPI_FID: RU8009.40(7B2) ; also on sheet 33
MEB2_CPI_VSYNC: RU8009.29(12B2) ; also on sheet 27
MEB2_CPI_WEn: RU8009.42(6B2) ; also on sheet 33
MEB3_GPMC_A8: RU8009.3(1B3) ; also on sheet 9
MEB3_GPMC_A9: RU8009.5(2B3) ; also on sheet 9
MEB3_GPMC_A10: RU8009.7(3B3) ; also on sheet 9
MEB3_GPMC_A11: RU8009.10(4B3) ; also on sheet 9
MEB3_GPMC_A12: RU8009.12(5B3) ; also on sheet 9
MEB3_GPMC_A13: RU8009.14(6B3) ; also on sheet 9
MEB3_GPMC_A14: RU8009.16(7B3) ; also on sheet 9
MEB3_GPMC_A15: RU8009.20(8B3) ; also on sheet 9
MFB1_RGMII0_RXC: RU8010.41(7B1) ; also on sheet 11
MFB1_RGMII0_RXCTL: RU8010.39(8B1) ; also on sheet 11
MFB1_RGMII0_RXD0: RU8010.30(12B1) ; also on sheet 11
MFB1_RGMII0_RXD1: RU8010.32(11B1) ; also on sheet 11
MFB1_RGMII0_RXD2: RU8010.34(10B1) ; also on sheet 11
MFB1_RGMII0_RXD3: RU8010.36(9B1) ; also on sheet 11
MFB1_RGMII0_TXC: RU8010.54(1B1) ; also on sheet 11
MFB1_RGMII0_TXCTL: RU8010.52(2B1) ; also on sheet 11
MFB1_RGMII0_TXD0: RU8010.43(6B1) ; also on sheet 11
MFB1_RGMII0_TXD1: RU8010.45(5B1) ; also on sheet 11
MFB1_RGMII0_TXD2: RU8010.47(4B1) ; also on sheet 11
MFB1_RGMII0_TXD3: RU8010.50(3B1) ; also on sheet 11
MFB2_RGMII0_RXC: RU8010.40(7B2) ; also on sheet 11
MFB2_RGMII0_RXCTL: RU8010.37(8B2) ; also on sheet 11
MFB2_RGMII0_RXD0: RU8010.29(12B2) ; also on sheet 11
MFB2_RGMII0_RXD1: RU8010.31(11B2) ; also on sheet 11
MFB2_RGMII0_RXD2: RU8010.33(10B2) ; also on sheet 11
MFB2_RGMII0_RXD3: RU8010.35(9B2) ; also on sheet 11
MFB2_RGMII0_TXC: RU8010.53(1B2) ; also on sheet 11
MFB2_RGMII0_TXCTL: RU8010.51(2B2) ; also on sheet 11
MFB2_RGMII0_TXD0: RU8010.42(6B2) ; also on sheet 11
MFB2_RGMII0_TXD1: RU8010.44(5B2) ; also on sheet 11
MFB2_RGMII0_TXD2: RU8010.46(4B2) ; also on sheet 11
MFB2_RGMII0_TXD3: RU8010.48(3B2) ; also on sheet 11
MFB3_MMC_CLK: R343.1 RU8010.16(7B3)
MFB3_MMC_CMD: R344.1 RU8010.20(8B3)
MFB3_MMC_DAT0: R342.1 RU8010.22(9B3)
MFB3_MMC_DAT1: R341.1 RU8010.24(10B3)
MFB3_MMC_DAT2: R340.1 RU8010.26(11B3)
MFB3_MMC_DAT3: R345.1 RU8010.28(12B3)
MHB1_UART3_CTSn: RU8011.52(2B1) ; also on sheet 10
MHB1_UART3_RTSn: RU8011.50(3B1) ; also on sheet 10
MHB1_UART3_RXD: RU8011.54(1B1) ; also on sheet 10
MHB1_UART3_TXD: RU8011.47(4B1) ; also on sheet 10
MHB2_SPI1_CS0: RU8011.46(4B2) U100.5(A4)
MHB2_SPI1_CS1: RU8011.44(5B2) U100.6(A5)
MHB2_SPI1_D0: RU8011.48(3B2) U100.3(A2)
MHB2_SPI1_D1: RU8011.51(2B2) U100.4(A3)
MHB2_SPI1_SCLK: RU8011.53(1B2) U100.1(A1)
MJB1_DCAN2_RX: U8009.7(2A2) ; also on sheet 32
MJB1_DCAN2_TX: U8009.5(1A2) ; also on sheet 32
MKB2_SPI4_CS0: U8010.8(A7) ; also on sheet 32
MKB2_SPI4_D0: U8010.6(A5) ; also on sheet 32
MKB2_SPI4_D1: U8010.7(A6) ; also on sheet 32
MKB2_SPI4_SCLK: U8010.5(A4) ; also on sheet 32
MMB1_GPIO1_17: U8011.4(A3) ; also on sheet 32
PM1_SCL: U1006.5(SCL) U1007.5(SCL) U1009.5(SCL) U1011.2(A0) U1011.5(SCL) U1012.5(SCL) U1013.2(A0) U1013.5(SCL) U1014.2(A0) U1014.5(SCL) U1015.5(SCL) U1016.5(SCL) U8024.5(SCL) U8025.5(SCL) U8026.1(A1) U8026.5(SCL) ; also on sheet 29
PM1_SDA: U1006.4(SDA) U1007.4(SDA) U1009.4(SDA) U1011.1(A1) U1011.4(SDA) U1012.2(A0) U1012.4(SDA) U1013.4(SDA) U1014.4(SDA) U1015.1(A1) U1015.4(SDA) U1016.4(SDA) U8024.1(A1) U8024.4(SDA) U8025.1(A1) U8025.2(A0) U8025.4(SDA) U8026.4(SDA) ; also on sheet 29
R_DCAN1_RX/GPIO4_10: U8009.6(2A1) ; also on sheet 7
R_DCAN1_TX/GPIO4_9: U8009.4(1A1) ; also on sheet 7
R_I2C1_SCL: U105.6(SCL) U117.1(SCL) ; also on sheet 7 8 13 28 29
R_I2C1_SDA: U105.5(SDA) U117.6(SDA) ; also on sheet 7 8 13 28 29
R_MDIO_MCLK/SPI4_D1/VIN2A_D0/GPIO3_17: R9123.2 R9125.2 ; also on sheet 7
R_RGMII0_RXC/CAM_STROBE/MMC_CLK/VIN2B_D0/GPIO3_25: RU8010.15(7A) ; also on sheet 7
R_RGMII0_RXCTL/CAM_SHUTTER/MMC_CMD/VIN2B_D1/GPIO3_26: RU8010.18(8A) ; also on sheet 7
R_RGMII0_RXD0/MMC_DAT3/VIN2B_D5/GPIO3_30: RU8010.27(12A) ; also on sheet 7
R_RGMII0_RXD1/MMC_DAT2/VIN2B_D4/GPIO3_29: RU8010.25(11A) ; also on sheet 7
R_RGMII0_RXD2/MMC_DAT1/VIN2B_D3/GPIO3_28: RU8010.23(10A) ; also on sheet 7
R_RGMII0_RXD3/MMC_DAT0/VIN2B_D2/GPIO3_27: RU8010.21(9A) ; also on sheet 7
R_RGMII0_TXC/CAM_STROBE/SPI4_SCLK/MMC_CLK/VIN2A_D2/GPIO3_19: RU8010.2(1A) ; also on sheet 7
R_RGMII0_TXCTL/CAM_SHUTTER/SPI4_CS0/MMC_CMD/VIN2A_D3/GPIO3_2: RU8010.4(2A) ; also on sheet 7
R_RGMII0_TXD0/MMC_DAT3/VIN2A_D7/GPIO3_24: RU8010.13(6A) ; also on sheet 7
R_RGMII0_TXD1/MMC_DAT2/VIN2A_D6/GPIO3_23: RU8010.11(5A) ; also on sheet 7
R_RGMII0_TXD2/eCAP1_IN_PWM1_OUT/MMC_DAT1/VIN2A_D5/GPIO3_22: RU8010.9(4A) ; also on sheet 7
R_RGMII0_TXD3/MMC_DAT0/VIN2A_D4/GPIO3_21: RU8010.6(3A) ; also on sheet 7
R_SPI1_CS0/UART3_TXD/GPIO4_3: RU8011.9(4A) ; also on sheet 7
R_SPI1_CS1/SPI3_CS1/TIMER6/EHRPWM1_TRIPZONE_INPUT/GPIO4_4: RU8011.11(5A) ; also on sheet 7
R_SPI1_D0/UART3_RTSn/GPIO4_2: RU8011.6(3A) ; also on sheet 7
R_SPI1_D1/UART3_CTSn/GPIO4_1: RU8011.4(2A) ; also on sheet 7
R_SPI1_SCLK/UART3_RXD/GPIO4_0: RU8011.2(1A) ; also on sheet 7
R_SPI2_CS0/UART3_TXD/EHRPWM1B/TIMER4/GPIO4_8: R9447.2 U8010.1(A1) U8043.1(~{CS}) ; also on sheet 7
R_SPI2_D1/UART3_CTSn/TIMER5/eCAP1_IN_PWM_OUT/GPIO4_6: R9448.2 U100.9(A8) U8043.2(DO) ; also on sheet 7
R_SPI2_SCLK/UART3_RXD/EHRPWM1A/TIMER3/GPIO4_5: R9445.1 U100.7(A6) U8043.6(SCLK) ; also on sheet 7
R_VIN1A_CLK0/CPI_PCLK/CLKOUT0/GPIO1_30: RU8008.2(1A) ; also on sheet 7
R_VIN1A_D00/CPI_DATA2/GPIO2_3: RU8008.11(5A) ; also on sheet 7
R_VIN1A_D01/CPI_DATA3/GPIO2_4: RU8008.13(6A) ; also on sheet 7
R_VIN1A_D02/CPI_DATA4/GPIO2_5: RU8008.15(7A) ; also on sheet 7
R_VIN1A_D03/CPI_DATA5/GPIO2_6: RU8008.18(8A) ; also on sheet 7
R_VIN1A_D04/CPI_DATA6/GPIO2_7: RU8008.21(9A) ; also on sheet 7
R_VIN1A_D05/CPI_DATA7/GPIO2_8: RU8008.23(10A) ; also on sheet 7
R_VIN1A_D06/CPI_DATA8/GPIO2_9: RU8008.25(11A) ; also on sheet 7
R_VIN1A_D07/CPI_DATA9/GPIO2_10: RU8008.27(12A) ; also on sheet 7
R_VIN1A_D08/CPI_DATA10/VIN1B_D0/GPMC_A8/SYS_NIRQ2/GPIO2_11: RU8009.2(1A) ; also on sheet 7
R_VIN1A_D09/CPI_DATA11/VIN1B_D1/GPMC_A9/SYS_NIRQ1/GPIO2_12: RU8009.4(2A) ; also on sheet 7
R_VIN1A_D10/CPI_DATA12/VIN1B_D2/GPMC_A10/SYS_NIRQ2/GPIO2_13: RU8009.6(3A) ; also on sheet 7
R_VIN1A_D11/CPI_DATA13/VIN1B_D3/GPMC_A11/SYS_NIRQ1/GPIO2_14: RU8009.9(4A) ; also on sheet 7
R_VIN1A_D12/CPI_DATA14/VIN1B_D4/GPMC_A12/DMA_EVT1/GPIO2_15: RU8009.11(5A) ; also on sheet 7
R_VIN1A_D13/CPI_WEn/VIN1B_D5/GPMC_A13/DMA_EVT2/GPIO2_16: RU8009.13(6A) ; also on sheet 7
R_VIN1A_D14/CPI_FID/VIN1B_D6/GPMC_A14/MCASP1_AXR14/GPIO2_17: RU8009.15(7A) ; also on sheet 7
R_VIN1A_D15/CPI_DATA15/VIN1B_D7/GPMC_A15/MCASP1_AXR15/GPIO2_18: RU8009.18(8A) ; also on sheet 7
R_VIN1A_DE0/CPI_HSYNC/VIN1B_CLK1/CLKOUT1/GPIO1_31: RU8008.4(2A) ; also on sheet 7
R_VIN1A_FLD0/CPI_VSYNC/VIN2B_CLK1/CLKOUT2/GPIO2_0: RU8009.27(12A) ; also on sheet 7
R_VIN1A_HSYNC0/CPI_DATA0/VIN1A_DE0/GPIO2_1: RU8008.6(3A) ; also on sheet 7
R_VIN1A_VSYNC0/CPI_DATA1/GPIO2_2: RU8008.9(4A) ; also on sheet 7
R_VIN2A_DE0/CAM_STROBE/VIN2B_HSYNC1/VIN2B_DE1/GPIO4_21: RU8009.23(10A) ; also on sheet 7
R_VIN2A_FLD0/CAM_SHUTTER/VIN2B_VSYNC1/GPIO4_22: RU8009.25(11A) ; also on sheet 7
RGB1_MDIO_D: R9124.1 ; also on sheet 11
RGB1_MDIO_MCLK: R9123.1 ; also on sheet 11
RGB2_MDIO_D: R9126.1 ; also on sheet 11
RGB2_MDIO_MCLK: R9125.1 ; also on sheet 11
RMB2_SPI3_CS0: U8011.8(A7) ; also on sheet 32
RMB2_SPI3_CS1: U8011.9(A8) ; also on sheet 32
RMB2_SPI3_D0: U8011.6(A5) ; also on sheet 32
RMB2_SPI3_D1: U8011.7(A6) ; also on sheet 32
RMB2_SPI3_SCLK: U8011.5(A4) ; also on sheet 32
SEL_MD_E0: RU8008.1(S0) RU8009.1(S0) ; also on sheet 26
SEL_MD_E1: RU8008.56(S1) RU8009.56(S1) ; also on sheet 26
SEL_MF0: RU8010.1(S0) ; also on sheet 26
SEL_MF1: RU8010.56(S1) ; also on sheet 26
SEL_MH0: RU8011.1(S0) ; also on sheet 26
SPI2_D0/UART3_RTSn/TIMER1/GPIO4_7/SYSBOOT7: R9443.2 U100.8(A7) U8043.5(DI) ; also on sheet 7 31
TEMP_ADD0: R625.1 R629.2 U117.4(ADD0)
VBUCK_3V3: C1027.2 C1028.2 C1030.2 C1032.2 C1033.2 C1034.2 C1035.2 C1036.2 C1037.2 C8148.2 C8149.2 C8150.2 R9347.1 U1006.6(VS) U1007.1(A1) U1007.2(A0) U1007.6(VS) U1009.2(A0) U1009.6(VS) U1011.6(VS) U1012.6(VS) U1013.1(A1) U1013.6(VS) U1014.6(VS) U1015.6(VS) U1016.1(A1) U1016.6(VS) U8024.2(A0) U8024.6(VS) U8024.8(VBUS) U8024.10(VIN+) U8025.6(VS) U8026.6(VS) ; also on sheet 12 15 29
VBUCK_5V0: R1026.1 U8025.8(VBUS) U8025.10(VIN+) ; also on sheet 12
VLIM_12V: R1028.1 R9386.1 U1011.8(VBUS) U1011.10(VIN+) U8026.8(VBUS) U8026.10(VIN+) ; also on sheet 12 28
VPIN_S1_3V3: U1006.9(VIN-) ; also on sheet 13
VPIN_S2_3V3: U1009.9(VIN-) ; also on sheet 13
VPIN_S3_3V3: U1012.9(VIN-) ; also on sheet 13
VPIN_S4_3V3: U1014.9(VIN-) ; also on sheet 13
VPO_1V8: J6104.3(E2) J6104.4(D2) J6104.9(E5) J6104.10(D5) R9384.1 RJ3.1 ; also on sheet 4 15
VPO_DDR_DV: J6105.3(E2) J6105.4(D2) J6105.9(E5) J6105.10(D5) R1014.1 R9385.1 RJ4.1 U1015.8(VBUS) U1015.10(VIN+) ; also on sheet 14
VPO_S1_AVS: J78.1(E1) J78.2(D1) R1010.1 RJ1.3 U1016.8(VBUS) U1016.10(VIN+) ; also on sheet 13
VPO_S2_AVS: J6103.1(E1) J6103.2(D1) R1016.1 RJ2.3 U1007.8(VBUS) U1007.10(VIN+) ; also on sheet 13
VPO_S3_1V8: J6104.1(E1) J6104.2(D1) R9384.2 RJ3.3 ; also on sheet 13
VPO_S4_DV: J6105.1(E1) J6105.2(D1) R9385.2 RJ4.3 ; also on sheet 13
VPRH_3V3: C527.1 C540.1 C8071.1 C8075.1 C8076.1 C8237.1 R9402.1 RU8008.55(S2) RU8009.55(S2) RU8010.55(S2) RU8011.55(S2) RU8011.56(S1) U54.5(VIO/NC) U100.19(VCCB) U8009.16(VCCB) U8010.19(VCCB) U8011.19(VCCB) U8042.5(VIO/NC) ; also on sheet 8 9 11 15 16 17 18 19 20 21 22 23 25 30 31 32
VPRH_5V0: C531.1 C8235.1 U54.3(VCC) U8042.3(VCC) ; also on sheet 14 16 17 20 21 23 25 26
VPRH_12V0: R9386.2 U8026.9(VIN-) ; also on sheet 7 21
VPRH_DV: C1.1 C12.1 C14.1 C15.1 C16.1 C233.1 C513.2 C523.2 C8070.2 C8072.1 C8073.1 C8074.1 P14.4(VDD) R14.1 R15.1 R16.1 R17.1 R18.1 R19.1 R327.1 R573.1 R575.1 R577.1 R629.1 R823.1 R9418.1 R9443.1 R9445.2 R9446.2 R9447.1 R9448.1 R9449.1 U77.1(VCC) U78.1(VCC) U79.1(VCC) U100.2(VCCA) U105.8(VCC) U117.5(V+) U8009.1(VCCA) U8009.2(1DIR) U8010.2(VCCA) U8011.2(VCCA) U8043.8(VCC) ; also on sheet 4 7 8 9 10 11 13 15 16 17 18 19 20 21 22 23 26 27 28 31
VSD_U122: C693.1 R823.2 U122.1(VCC)
VSYS_3V3: R9347.2 U1006.8(VBUS) U1006.10(VIN+) U1009.8(VBUS) U1009.10(VIN+) U1012.8(VBUS) U1012.10(VIN+) U1014.8(VBUS) U1014.10(VIN+) U8024.9(VIN-) ; also on sheet 6 12 13 14 16 26 27 32
VSYS_5V0: C8060.1 C8061.1 C8062.1 C8063.1 R1026.2 RU8008.17(VCC.1) RU8009.17(VCC.1) RU8010.17(VCC.1) RU8011.17(VCC.1) U8025.9(VIN-) ; also on sheet 14 30 32
VSYS_12V: R1028.2 U1011.9(VIN-) ; also on sheet 12 29
N27861126: P14.10(INSERT_COM) R304.1
N30065266: R9449.2 U8043.3(~{WP})
N30065268: R9446.1 U8043.7(~{HOLD})

Not connected (* = marked no-connect by the designer): J6106 1* 19; P14 11 12 13 14 15; RU8008 3(1B3) 5(2B3) 7(3B3) 10(4B3) 12(5B3) 14(6B3) 16(7B3) 20(8B3) 22(9B3) 24(10B3) 26(11B3) 28(12B3); RU8009 21(9A) 22(9B3) 24(10B3) 26(11B3) 28(12B3) 31(11B2) 33(10B2) 35(9B2) 36(9B1); RU8010 3(1B3) 5(2B3) 7(3B3) 10(4B3) 12(5B3) 14(6B3); RU8011 3(1B3) 5(2B3) 7(3B3) 10(4B3) 12(5B3) 13(6A) 14(6B3) 15(7A) 16(7B3) 18(8A) 20(8B3) 21(9A) 22(9B3) 23(10A) 24(10B3) 25(11A) 26(11B3) 27(12A) 28(12B3) 29(12B2) 30(12B1) 31(11B2) 32(11B1) 33(10B2) 34(10B1) 35(9B2) 36(9B1) 37(8B2) 39(8B1) 40(7B2) 41(7B1) 42(6B2) 43(6B1); U77 2(NC.2); U78 2(NC.2); U79 2(NC.2); U122 2(NC.2) 3(IO1); U1006 3(ALERT/NC.3); U1007 3(ALERT/NC.3); U1009 3(ALERT/NC.3); U1011 3(ALERT/NC.3); U1012 3(ALERT/NC.3); U1013 3(ALERT/NC.3); U1014 3(ALERT/NC.3); U1015 3(ALERT/NC.3); U1016 3(ALERT/NC.3); U8010 3(A2) 4(A3) 9(A8) 12(B8) 17(B3) 18(B2); U8011 1(A1) 3(A2) 18(B2) 20(B1); U8024 3(ALERT/NC.3); U8025 3(ALERT/NC.3); U8026 3(ALERT/NC.3)

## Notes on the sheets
sheet 34
- Board Mux D
- Board Mux F
- TDA3x
- VIP CPLD
- TDA3x
- RGMII0 ENET
- ISS CPLD
- RGMII0 EXP
- (open)
- SD CARD
- Board Mux E
- Board Mux G
- TDA3x
- VIP CPLD
- TDA3x
- RGMII0 ENET
- ISS CPLD
- RGMII0/1 EXP
- GPMC NOR/EXP
- Board Mux H
- TDA3x
- TERMINAL
- SPI EXP
- (open)
sheet 35
- DCAN1/2 Headers
- CAN1 Transceiver/Header
- Silkscreen: DCAN1
- Silkscreen: CANBUS1
- HVDA541QDRQ1
  TCAN1042HGV-Q1
- ER26
- Silkscreen: DCAN2
- [DCAN1_STB]
- Silkscreen: CANBUS2
- SPI1
- HVDA541QDRQ1
  TCAN1042HGV-Q1
- CAN2 Transceiver/Header
- Safety MCU/SPI Interface
- SPI2
- 57
- 58
- [EQEPA] [57]
- [EQEPI] [59]
- [NHET22] [60]
- [OPEN [58]
- [EQEPB] [61]
- [NHET24] [62]
- [EQEPS] [63]
- [OPEN] [64]
- [OPEN] [65]
- [ADEVT_NHET28] [66]
- [GIOA7] [67]
- [OPEN] [68]
- [GIOA6_SPI2CS1] [69]
- [GND] [71]
- [GIOA1_SPI3CS2] [72]
- [RSTN] [70]
- [GIOA0_SPI3CS3] [73]
- [SPI3SOMI] [74]
- [SPI3SIMO] [75]
- [SPI3CS0] [76]
- [GIOA2_SPI3CS1] [77]
- [SPI3CLK] [78]
- [SPI3ENA] [79]
- [GND] [80]
- MCU CANNOT DRIVE SOC UNTIL
  AFTER SOC BOOTS.
- SPI4
- Silkscreen: MCU/SPI
- SPI3
sheet 36
- Board EEPROM
- I2C Address: 0x51
- Temperature Sensor
- SPI MEMORY 8M BYTE
- ER28
- I2C Address: 0x48
- 8M BYTE
- Note: Place sensor close to processor.
- SD CARD
- [SD_CARD_DETECTn]
sheet 37
- 1-2 : PWR-BENCH SENSE
- 3-4 : PWR-BENCH SOURCE (2 VIA PER PIN)
- 100-0000
- 9-10 : PWR-BENCH FEEDBACK
- 100-0100
- RTx AT THE SOC, FEEDBACK IS
  ROUTED NET. RTx WILL BE
  REMOVED IN FINAL LAYOUT.
- 100-0001
- 100-1001
- 100-0010
- 100-1010
- 100-0101
- 100-0011
- 100-1011
- 100-0111
- 100-1100
- 100-1000
